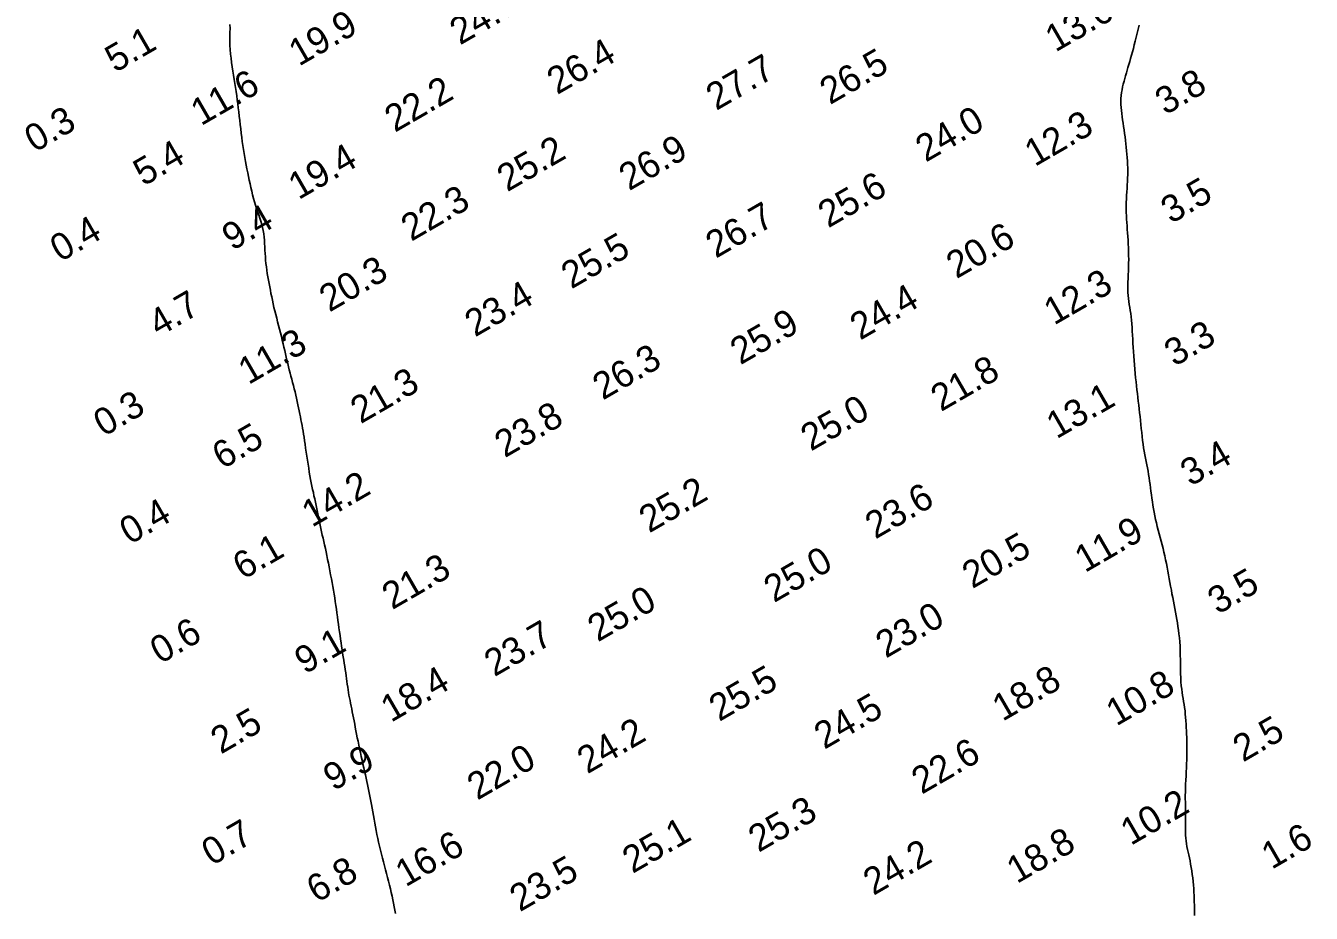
# Model space of a CAD drawing. Extents: x 3024098 to 3056816, y 418252 to 509144.
# Drawn here: x 3028028.3 to 3028267.5, y 427326.7 to 427491.8 of the extents above; entities that cross this region are included whole.
import ezdxf

# ---------------------------------------------------------------- set-up
doc = ezdxf.new("R2010")
doc.units = 0
doc.layers.add('V-CHAN-CONT-EL10', color=7, linetype='Continuous')
doc.layers.add('V-TOPO-SOUN-0911', color=7, linetype='Continuous')

msp = doc.modelspace()

# ---------------------------------------------------------------- linework, layer by layer
at = {"layer": 'V-CHAN-CONT-EL10'}
for points in [[(3028097.15, 427326.65), (3028097.02, 427327.27), (3028096.89, 427327.9), (3028096.76, 427328.55), (3028096.62, 427329.21), (3028096.49, 427329.87), (3028096.34, 427330.55), (3028096.19, 427331.24), (3028096.02, 427331.93), (3028095.85, 427332.64), (3028095.66, 427333.35), (3028095.47, 427334.07), (3028095.27, 427334.79), (3028095.08, 427335.51), (3028094.88, 427336.24), (3028094.69, 427336.97), (3028094.51, 427337.7), (3028094.33, 427338.43), (3028094.16, 427339.16), (3028093.99, 427339.89), (3028093.83, 427340.62), (3028093.68, 427341.34), (3028093.53, 427342.06), (3028093.39, 427342.77), (3028093.26, 427343.48), (3028093.14, 427344.19), (3028093.02, 427344.89), (3028092.9, 427345.57), (3028092.79, 427346.25), (3028092.67, 427346.91), (3028092.56, 427347.56), (3028092.44, 427348.19), (3028092.32, 427348.81), (3028092.2, 427349.42), (3028092.07, 427350.02), (3028091.94, 427350.62), (3028091.81, 427351.22), (3028091.67, 427351.83), (3028091.53, 427352.45), (3028091.38, 427353.1), (3028091.23, 427353.76), (3028091.07, 427354.45), (3028090.92, 427355.15), (3028090.76, 427355.85), (3028090.6, 427356.57), (3028090.45, 427357.28), (3028090.3, 427357.98), (3028090.16, 427358.67), (3028090.02, 427359.35), (3028089.9, 427360.01), (3028089.77, 427360.65), (3028089.65, 427361.28), (3028089.54, 427361.89), (3028089.43, 427362.48), (3028089.32, 427363.06), (3028089.21, 427363.62), (3028089.1, 427364.17), (3028088.99, 427364.7), (3028088.88, 427365.22), (3028088.78, 427365.74), (3028088.68, 427366.24), (3028088.58, 427366.75), (3028088.48, 427367.25), (3028088.4, 427367.75), (3028088.31, 427368.26), (3028088.24, 427368.77), (3028088.16, 427369.29), (3028088.09, 427369.81), (3028088.02, 427370.34), (3028087.94, 427370.88), (3028087.87, 427371.44), (3028087.78, 427372), (3028087.69, 427372.59), (3028087.6, 427373.18), (3028087.5, 427373.79), (3028087.4, 427374.41), (3028087.3, 427375.04), (3028087.2, 427375.69), (3028087.1, 427376.34), (3028087, 427377.01), (3028086.9, 427377.68), (3028086.81, 427378.36), (3028086.71, 427379.05), (3028086.62, 427379.75), (3028086.53, 427380.45), (3028086.43, 427381.15), (3028086.34, 427381.85), (3028086.24, 427382.56), (3028086.14, 427383.26), (3028086.04, 427383.96), (3028085.93, 427384.66), (3028085.82, 427385.36), (3028085.7, 427386.06), (3028085.59, 427386.77), (3028085.46, 427387.48), (3028085.34, 427388.2), (3028085.21, 427388.92), (3028085.07, 427389.65), (3028084.94, 427390.38), (3028084.8, 427391.1), (3028084.66, 427391.82), (3028084.51, 427392.52), (3028084.37, 427393.21), (3028084.23, 427393.89), (3028084.08, 427394.55), (3028083.94, 427395.19), (3028083.8, 427395.82), (3028083.66, 427396.43), (3028083.52, 427397.04), (3028083.38, 427397.65), (3028083.24, 427398.25), (3028083.11, 427398.85), (3028082.98, 427399.47), (3028082.85, 427400.08), (3028082.72, 427400.7), (3028082.6, 427401.31), (3028082.47, 427401.93), (3028082.35, 427402.54), (3028082.22, 427403.15), (3028082.1, 427403.75), (3028081.97, 427404.35), (3028081.85, 427404.94), (3028081.72, 427405.54), (3028081.59, 427406.14), (3028081.47, 427406.76), (3028081.34, 427407.4), (3028081.22, 427408.06), (3028081.1, 427408.74), (3028080.98, 427409.46), (3028080.87, 427410.21), (3028080.75, 427410.96), (3028080.64, 427411.72), (3028080.53, 427412.47), (3028080.42, 427413.21), (3028080.32, 427413.92), (3028080.22, 427414.59), (3028080.12, 427415.22), (3028080.03, 427415.81), (3028079.93, 427416.37), (3028079.84, 427416.91), (3028079.74, 427417.43), (3028079.65, 427417.95), (3028079.55, 427418.47), (3028079.44, 427419), (3028079.33, 427419.55), (3028079.22, 427420.12), (3028079.1, 427420.7), (3028078.98, 427421.28), (3028078.85, 427421.88), (3028078.72, 427422.47), (3028078.59, 427423.07), (3028078.44, 427423.67), (3028078.3, 427424.26), (3028078.15, 427424.84), (3028077.99, 427425.43), (3028077.84, 427426.01), (3028077.68, 427426.59), (3028077.53, 427427.17), (3028077.38, 427427.75), (3028077.23, 427428.34), (3028077.08, 427428.93), (3028076.94, 427429.53), (3028076.8, 427430.13), (3028076.66, 427430.74), (3028076.52, 427431.36), (3028076.38, 427431.99), (3028076.23, 427432.63), (3028076.07, 427433.28), (3028075.91, 427433.95), (3028075.74, 427434.62), (3028075.56, 427435.31), (3028075.38, 427435.99), (3028075.21, 427436.68), (3028075.03, 427437.37), (3028074.86, 427438.05), (3028074.69, 427438.73), (3028074.53, 427439.39), (3028074.38, 427440.05), (3028074.24, 427440.7), (3028074.1, 427441.34), (3028073.97, 427441.97), (3028073.85, 427442.6), (3028073.73, 427443.22), (3028073.61, 427443.84), (3028073.5, 427444.46), (3028073.39, 427445.08), (3028073.29, 427445.69), (3028073.2, 427446.3), (3028073.12, 427446.92), (3028073.04, 427447.53), (3028072.98, 427448.14), (3028072.93, 427448.76), (3028072.89, 427449.38), (3028072.85, 427450), (3028072.83, 427450.62), (3028072.79, 427451.24), (3028072.75, 427451.86), (3028072.7, 427452.47), (3028072.62, 427453.07), (3028072.52, 427453.67), (3028072.4, 427454.25), (3028072.24, 427454.83), (3028072.07, 427455.41), (3028071.88, 427455.99), (3028071.69, 427456.57), (3028071.48, 427457.16), (3028071.28, 427457.75), (3028071.08, 427458.37), (3028070.89, 427459), (3028070.71, 427459.64), (3028070.54, 427460.3), (3028070.38, 427460.98), (3028070.22, 427461.66), (3028070.07, 427462.34), (3028069.92, 427463.04), (3028069.78, 427463.73), (3028069.64, 427464.43), (3028069.5, 427465.13), (3028069.36, 427465.83), (3028069.23, 427466.54), (3028069.1, 427467.26), (3028068.98, 427467.98), (3028068.86, 427468.72), (3028068.75, 427469.47), (3028068.64, 427470.24), (3028068.54, 427471.01), (3028068.44, 427471.8), (3028068.34, 427472.59), (3028068.25, 427473.38), (3028068.16, 427474.17), (3028068.07, 427474.96), (3028067.97, 427475.74), (3028067.88, 427476.5), (3028067.79, 427477.26), (3028067.69, 427478.01), (3028067.59, 427478.76), (3028067.49, 427479.51), (3028067.38, 427480.26), (3028067.26, 427481.02), (3028067.15, 427481.78), (3028067.02, 427482.55), (3028066.89, 427483.33), (3028066.77, 427484.12), (3028066.65, 427484.91), (3028066.54, 427485.71), (3028066.46, 427486.51), (3028066.39, 427487.32), (3028066.34, 427488.12), (3028066.33, 427488.92), (3028066.33, 427489.72), (3028066.34, 427490.51), (3028066.35, 427491.28), (3028066.34, 427492.02)], [(3028235.43, 427491.87), (3028235.27, 427491.13), (3028235.1, 427490.39), (3028234.92, 427489.65), (3028234.74, 427488.93), (3028234.55, 427488.23), (3028234.37, 427487.55), (3028234.19, 427486.89), (3028234.02, 427486.27), (3028233.85, 427485.68), (3028233.69, 427485.11), (3028233.53, 427484.56), (3028233.37, 427484.03), (3028233.22, 427483.51), (3028233.07, 427482.99), (3028232.93, 427482.48), (3028232.78, 427481.96), (3028232.64, 427481.44), (3028232.5, 427480.92), (3028232.38, 427480.39), (3028232.27, 427479.86), (3028232.18, 427479.33), (3028232.11, 427478.79), (3028232.07, 427478.24), (3028232.06, 427477.7), (3028232.06, 427477.14), (3028232.1, 427476.58), (3028232.15, 427476.01), (3028232.21, 427475.43), (3028232.29, 427474.84), (3028232.37, 427474.25), (3028232.46, 427473.64), (3028232.55, 427473.02), (3028232.64, 427472.39), (3028232.73, 427471.75), (3028232.82, 427471.1), (3028232.9, 427470.45), (3028232.98, 427469.8), (3028233.05, 427469.16), (3028233.12, 427468.51), (3028233.18, 427467.88), (3028233.23, 427467.24), (3028233.27, 427466.61), (3028233.3, 427465.98), (3028233.32, 427465.35), (3028233.33, 427464.72), (3028233.33, 427464.08), (3028233.31, 427463.44), (3028233.29, 427462.8), (3028233.25, 427462.15), (3028233.21, 427461.5), (3028233.17, 427460.85), (3028233.12, 427460.2), (3028233.09, 427459.55), (3028233.06, 427458.91), (3028233.04, 427458.28), (3028233.04, 427457.65), (3028233.05, 427457.03), (3028233.07, 427456.42), (3028233.1, 427455.8), (3028233.14, 427455.17), (3028233.19, 427454.54), (3028233.23, 427453.9), (3028233.28, 427453.24), (3028233.33, 427452.57), (3028233.38, 427451.89), (3028233.42, 427451.18), (3028233.45, 427450.48), (3028233.48, 427449.76), (3028233.49, 427449.04), (3028233.5, 427448.32), (3028233.49, 427447.59), (3028233.47, 427446.87), (3028233.44, 427446.16), (3028233.41, 427445.45), (3028233.38, 427444.76), (3028233.35, 427444.08), (3028233.33, 427443.42), (3028233.33, 427442.78), (3028233.35, 427442.17), (3028233.38, 427441.58), (3028233.44, 427441.01), (3028233.52, 427440.46), (3028233.6, 427439.91), (3028233.69, 427439.36), (3028233.79, 427438.8), (3028233.88, 427438.23), (3028233.96, 427437.63), (3028234.02, 427437.01), (3028234.08, 427436.35), (3028234.13, 427435.67), (3028234.18, 427434.97), (3028234.22, 427434.24), (3028234.26, 427433.5), (3028234.3, 427432.73), (3028234.34, 427431.95), (3028234.39, 427431.15), (3028234.45, 427430.34), (3028234.51, 427429.53), (3028234.58, 427428.71), (3028234.65, 427427.9), (3028234.72, 427427.09), (3028234.8, 427426.3), (3028234.88, 427425.53), (3028234.96, 427424.78), (3028235.04, 427424.05), (3028235.13, 427423.34), (3028235.21, 427422.63), (3028235.29, 427421.93), (3028235.38, 427421.22), (3028235.46, 427420.52), (3028235.54, 427419.8), (3028235.61, 427419.07), (3028235.69, 427418.33), (3028235.76, 427417.59), (3028235.84, 427416.84), (3028235.92, 427416.1), (3028236, 427415.37), (3028236.09, 427414.65), (3028236.19, 427413.95), (3028236.29, 427413.28), (3028236.41, 427412.62), (3028236.52, 427411.98), (3028236.64, 427411.35), (3028236.76, 427410.73), (3028236.88, 427410.12), (3028236.99, 427409.51), (3028237.1, 427408.9), (3028237.2, 427408.29), (3028237.29, 427407.67), (3028237.38, 427407.05), (3028237.47, 427406.43), (3028237.55, 427405.8), (3028237.64, 427405.17), (3028237.73, 427404.53), (3028237.82, 427403.89), (3028237.92, 427403.24), (3028238.02, 427402.59), (3028238.14, 427401.93), (3028238.25, 427401.27), (3028238.38, 427400.61), (3028238.52, 427399.94), (3028238.67, 427399.28), (3028238.83, 427398.6), (3028238.99, 427397.93), (3028239.17, 427397.26), (3028239.35, 427396.58), (3028239.53, 427395.9), (3028239.71, 427395.22), (3028239.89, 427394.54), (3028240.06, 427393.85), (3028240.23, 427393.15), (3028240.38, 427392.45), (3028240.53, 427391.75), (3028240.67, 427391.04), (3028240.8, 427390.33), (3028240.93, 427389.62), (3028241.06, 427388.91), (3028241.18, 427388.21), (3028241.31, 427387.5), (3028241.44, 427386.8), (3028241.56, 427386.11), (3028241.69, 427385.42), (3028241.83, 427384.73), (3028241.95, 427384.05), (3028242.08, 427383.37), (3028242.21, 427382.7), (3028242.33, 427382.03), (3028242.45, 427381.36), (3028242.56, 427380.7), (3028242.67, 427380.03), (3028242.77, 427379.35), (3028242.86, 427378.64), (3028242.94, 427377.92), (3028243, 427377.17), (3028243.05, 427376.38), (3028243.09, 427375.55), (3028243.11, 427374.7), (3028243.12, 427373.83), (3028243.13, 427372.96), (3028243.14, 427372.1), (3028243.16, 427371.27), (3028243.19, 427370.47), (3028243.23, 427369.71), (3028243.29, 427369.01), (3028243.36, 427368.37), (3028243.45, 427367.76), (3028243.54, 427367.18), (3028243.64, 427366.62), (3028243.73, 427366.07), (3028243.82, 427365.52), (3028243.91, 427364.95), (3028243.98, 427364.36), (3028244.04, 427363.75), (3028244.1, 427363.14), (3028244.15, 427362.51), (3028244.19, 427361.88), (3028244.22, 427361.25), (3028244.25, 427360.64), (3028244.27, 427360.03), (3028244.29, 427359.44), (3028244.31, 427358.86), (3028244.33, 427358.29), (3028244.33, 427357.71), (3028244.34, 427357.12), (3028244.34, 427356.51), (3028244.33, 427355.88), (3028244.31, 427355.21), (3028244.28, 427354.5), (3028244.25, 427353.76), (3028244.21, 427353), (3028244.17, 427352.23), (3028244.14, 427351.47), (3028244.1, 427350.71), (3028244.07, 427349.97), (3028244.05, 427349.27), (3028244.04, 427348.6), (3028244.04, 427347.97), (3028244.05, 427347.36), (3028244.06, 427346.78), (3028244.07, 427346.22), (3028244.08, 427345.67), (3028244.09, 427345.12), (3028244.1, 427344.57), (3028244.09, 427344.02), (3028244.09, 427343.46), (3028244.08, 427342.9), (3028244.08, 427342.34), (3028244.08, 427341.78), (3028244.1, 427341.23), (3028244.13, 427340.68), (3028244.17, 427340.14), (3028244.24, 427339.62), (3028244.33, 427339.1), (3028244.43, 427338.58), (3028244.55, 427338.06), (3028244.67, 427337.53), (3028244.79, 427336.98), (3028244.91, 427336.42), (3028245.03, 427335.83), (3028245.14, 427335.22), (3028245.24, 427334.58), (3028245.33, 427333.93), (3028245.42, 427333.26), (3028245.49, 427332.6), (3028245.55, 427331.93), (3028245.6, 427331.28), (3028245.65, 427330.63), (3028245.68, 427330.01), (3028245.7, 427329.41), (3028245.71, 427328.8), (3028245.72, 427328.2), (3028245.73, 427327.57), (3028245.74, 427326.93), (3028245.75, 427326.25)]]:
    msp.add_lwpolyline(points, dxfattribs=at)

# ---------------------------------------------------------------- texts
at = {"layer": 'V-TOPO-SOUN-0911'}
for s, p in [('24.7 ', (3028109.12, 427488.08)), ('13.6 ', (3028219.88, 427486.77)), ('19.9 ', (3028079.17, 427484.14)), ('5.1', (3028044.99, 427482.95)), ('26.4 ', (3028127.2, 427478.86)), ('26.5 ', (3028177.94, 427476.99)), ('27.7 ', (3028156.79, 427475.91)), ('11.6 ', (3028060.95, 427473.06)), ('22.2 ', (3028097.01, 427471.84)), ('3.8', (3028240.32, 427475.06)), ('0.3', (3028030.02, 427468.11)), ('24.0 ', (3028195.75, 427466.29)), ('12.3 ', (3028216.04, 427465.48)), ('5.4', (3028050.26, 427461.84)), ('25.2 ', (3028117.91, 427460.78)), ('26.9 ', (3028140.58, 427460.98)), ('19.4 ', (3028079.1, 427459.31)), ('25.6 ', (3028177.62, 427454.06)), ('3.5', (3028241.39, 427454.85)), ('22.3 ', (3028100.06, 427451.57)), ('9.4', (3028066.76, 427449.83)), ('26.7 ', (3028156.72, 427448.42)), ('0.4', (3028034.77, 427447.73)), ('25.5 ', (3028129.84, 427442.71)), ('20.6 ', (3028201.47, 427444.62)), ('20.3 ', (3028084.84, 427438.41)), ('12.3 ', (3028219.62, 427435.98)), ('23.4 ', (3028111.91, 427433.78)), ('4.7', (3028053.08, 427433.82)), ('24.4 ', (3028183.56, 427433.19)), ('25.9 ', (3028161.28, 427428.6)), ('3.3', (3028242.02, 427428.28)), ('11.3 ', (3028069.78, 427424.92)), ('26.3 ', (3028135.69, 427422.04)), ('21.8 ', (3028198.59, 427419.9)), ('21.3 ', (3028090.65, 427417.64)), ('13.1 ', (3028220.09, 427414.83)), ('0.3', (3028042.85, 427415.25)), ('25.0 ', (3028174.39, 427412.55)), ('23.8 ', (3028117.45, 427411.31)), ('6.5', (3028064.92, 427409.18)), ('3.4', (3028245.01, 427406)), ('14.2 ', (3028081.59, 427398.38)), ('25.2 ', (3028144.32, 427397.33)), ('23.6 ', (3028186.38, 427396.19)), ('0.4', (3028047.7, 427395.17)), ('11.9 ', (3028225.36, 427389.95)), ('6.1', (3028068.75, 427388.63)), ('20.5 ', (3028204.42, 427386.97)), ('25.0 ', (3028167.53, 427384.37)), ('21.3 ', (3028096.52, 427383.06)), ('3.5', (3028250.09, 427382.18)), ('25.0 ', (3028134.76, 427377.06)), ('23.0 ', (3028188.34, 427374.04)), ('0.6', (3028053.38, 427372.97)), ('9.1', (3028080.26, 427371.07)), ('23.7 ', (3028115.52, 427370.59)), ('18.4 ', (3028096.29, 427362.1)), ('25.5 ', (3028157.34, 427362.26)), ('18.8 ', (3028210.04, 427362.29)), ('10.8 ', (3028231.2, 427361.41)), ('24.5 ', (3028176.89, 427357.08)), ('2.5', (3028064.65, 427356.2)), ('24.2 ', (3028132.81, 427352.52)), ('2.5', (3028254.78, 427354.72)), ('9.9', (3028085.59, 427349.34)), ('22.0 ', (3028112.35, 427347.63)), ('22.6 ', (3028195.01, 427348.72)), ('25.3 ', (3028164.66, 427337.92)), ('10.2 ', (3028233.89, 427339.2)), ('0.7', (3028062.96, 427335.43)), ('25.1 ', (3028141.22, 427333.99)), ('1.6', (3028260.1, 427334.75)), ('16.6 ', (3028099.01, 427331.49)), ('18.8 ', (3028212.7, 427332.11)), ('24.2 ', (3028186.02, 427329.91)), ('6.8', (3028082.48, 427328.54)), ('23.5 ', (3028120.26, 427326.86))]:
    msp.add_text(s, height=5, rotation=30, dxfattribs=at).set_placement(p)

doc.saveas('drawing.dxf')
